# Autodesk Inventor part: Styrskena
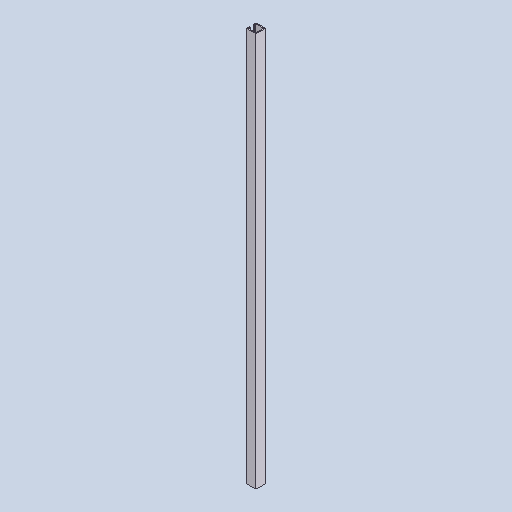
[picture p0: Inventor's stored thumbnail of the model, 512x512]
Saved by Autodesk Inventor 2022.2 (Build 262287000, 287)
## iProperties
Created: 2019-06
Part Number: Styrskena
Material: Aluminum 6061, Welded
Document SubType Name: Modeling
Designer: cl
Density: 2.7 g/cm^3
Appearance: Weld - Aluminum
Author: cl
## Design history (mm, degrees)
sketch "Sketch1"
  geometry: L1 (0, 0)-(50, 0); L2 (50, 0)-(50, -15); L3 (50, -35)-(50, -50); L4 (50, -50)-(0, -50); L5 (0, -50)-(0, 0); L6 (50, -15)-(45, -15); L7 (45, -15)-(45, -5); L8 (45, -5)-(5, -5); L9 (5, -5)-(5, -45); L10 (5, -45)-(45, -45); L11 (45, -45)-(45, -35); L12 (45, -35)-(50, -35)
  constraints: 24 end point, 7 perpendicular, 4 point on line, 2 horizontal, 1 parallel
  dimensions: "d0" = 50 distance of L1.start L1.end; "d1" = 15 distance of L1.end L2.end; "d2" = 15 distance of L3.start L3.end; "d3" = 50 distance of L4.end L1.start; "d5" = 5 distance of L2.end L6.end; "d6" = 10 distance of L6.end L7.end; "d7" = 10 distance of L10.end L11.end; "d9" = 5 distance between parallel lines of L5 L9
extrude "Extrusion1" new body sketch "Sketch1" distance "d10" = 2065 (computed from BladBredd); taper "d11" = 0 deg
body "Solid1"
other parameters: "BladBredd" = 987.5, "Fönsterhöjd" = 862, "Blad2" = 1012.5, "Blad3" = 0, "Blad4" = 0, "Blad5" = 1012.5, "Blad6" = 2025, "MGJ12Djup" = 0, "MGJ12Bredd" = 0, "MGJ2Djup" = 0, "MGJ2Bredd" = 5012.5, "MGJ56Djup" = 0, "MGJ56Bredd" = 0, "MGJ23Djup" = 48, "MGJ45Djup" = 48, "GarageRegel5" = 0, "GarageRegel6" = 0
